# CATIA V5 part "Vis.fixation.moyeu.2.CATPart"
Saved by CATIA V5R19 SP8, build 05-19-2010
Part number: Vis.fixation.moyeu.2
Bounding box of the stored display mesh (mm): x -24 to -18, y -1.5 to 1.5, z -1.5 to 1.5
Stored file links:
  G:\EU_thinkMotion\CFAO_2010\MMS_groupe3\MMS_groupe3\jbonnamy\jbonnamy_cfao\Vis.fixation.moyeu.2.CATPart
  C:\Users\Micheline\Desktop\projet CFAO\Nouveau dossier\temp\Nouveau dossier\Vis.fixation.CATPart
  G:\EU_thinkMotion\CFAO_2010\MMS_groupe3\MMS_groupe3\jbonnamy\jbonnamy_cfao\jbonnamy_suspension.arriere.directionnelle.CATProduct
  G:\EU_thinkMotion\CFAO_2010\MMS_groupe3\MMS_groupe3\jbonnamy\jbonnamy_cfao\Vis.fixation.moyeu.1.CATPart
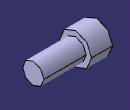
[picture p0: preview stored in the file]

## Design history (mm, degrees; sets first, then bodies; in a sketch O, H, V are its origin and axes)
External parameters (linked from other documents)
  External.Epaisseur.support.10 = 1.5 mm
  External.Diametre.vis.fixation = 2 mm
Set1
  DatumSurface1: linked copy from another document
Body1 (main body)
  Sketch1 on DatumSurface1, origin (-22, 0, 0), H (0, 1, 0), V (0, 0, 1)
    circle A1 centre (0, 0) radius 1
    radius A1 = 1 {= External.Diametre.vis.fixation /2}
  Pad1: profile Sketch1, direction (1, 0, 0), length 4 {= 2*External.Epaisseur.support.10 +1mm}
  Sketch2 on DatumSurface1, origin (-22, 0, 0), H (0, 1, 0), V (0, 0, 1)
    circle A1 centre (0, 0) radius 1.5
    radius A1 = 1.5 {= 3*External.Diametre.vis.fixation /4}
  Pad2: profile Sketch2, direction (-1, 0, 0), length 2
